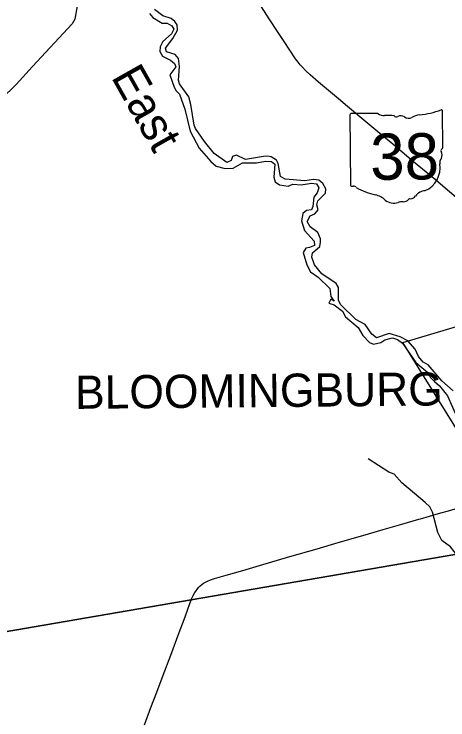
# Model space of a CAD drawing. Extents: x -51392 to 1635000, y 156707 to 696232.
# Drawn here: x 142132 to 148661, y 507736 to 518358 of the extents above; entities that cross this region are included whole.
import ezdxf

# ---------------------------------------------------------------- set-up
doc = ezdxf.new("R2010")
doc.units = 0
for name, color, linetype in [('GM_X_Corporation', 7, 'Continuous'), ('GM_X_Corporation_Text', 7, 'Continuous'), ('GM_X_Minor_River', 7, 'Continuous'), ('GM_X_Minor_River_Text', 7, 'Continuous'), ('GM_X_State_Route', 7, 'Continuous'), ('GM_X_State_Shield', 7, 'Continuous'), ('GM_X_Township', 7, 'Continuous')]:
    doc.layers.add(name, color=color, linetype=linetype)

msp = doc.modelspace()

# ---------------------------------------------------------------- linework, layer by layer
at = {"layer": 'GM_X_Corporation'}
msp.add_lwpolyline([(151122, 510634), (149846, 510420), (147983, 513415), (149817, 513960), (149380, 514705), (149899, 514933), (151298, 515355), (151165, 515855), (151597, 515995), (154267, 511567), (151620, 510720), (151716, 510504), (151268, 510327)], close=True, dxfattribs=at)
at = {"layer": 'GM_X_Minor_River'}
for points in [[(144055, 518872), (143223, 518622), (143173, 518604), (143109, 518555), (143080, 518482), (143046, 518284), (143005, 518212), (142408, 517569), (142163, 517297), (141940, 517082), (141639, 516862), (141521, 516751), (141472, 516673), (141395, 516408), (141367, 516342), (141275, 516249), (141124, 516197), (140980, 516203)], [(144172, 518369), (144218, 518307), (144362, 518222), (144434, 518220), (144504, 518183), (144538, 518129), (144503, 518061), (144371, 517945), (144331, 517865), (144326, 517795), (144364, 517723), (144488, 517663), (144546, 517614), (144566, 517564), (144475, 517446), (144542, 517256), (144572, 517204), (144620, 517151), (144703, 516927), (144782, 516596), (144915, 516339), (145092, 516138), (145172, 516070), (145308, 516035), (145430, 516039), (145572, 516121), (145780, 516122), (145915, 516146), (146005, 516139), (146056, 516097), (146040, 515905), (146063, 515833), (146127, 515790), (146257, 515768), (146329, 515796), (146455, 515789), (146608, 515813), (146682, 515803), (146717, 515744), (146693, 515668), (146641, 515604), (146626, 515464), (146606, 515412), (146534, 515402), (146478, 515355), (146459, 515246), (146501, 515100), (146646, 514939), (146654, 514877), (146578, 514845), (146522, 514834), (146485, 514768), (146537, 514583), (146592, 514477), (146706, 514400), (146884, 514229), (146899, 514107), (146951, 514039), (146897, 514067), (146871, 514009), (146949, 513983), (147074, 513886), (147120, 513804), (147311, 513643), (147379, 513521), (147483, 513414), (147543, 513390), (147653, 513414), (147711, 513456), (147827, 513485), (147905, 513463), (147979, 513407), (148176, 513117), (148359, 512963), (148393, 512896), (148459, 512828), (148535, 512764), (148654, 512615), (148807, 512274)], [(148742, 512687), (148569, 512838), (148362, 513077), (148288, 513119), (148218, 513203), (148169, 513316), (148057, 513440), (147941, 513503), (147777, 513551), (147587, 513484), (147517, 513540), (147414, 513687), (147276, 513763), (147045, 513988), (147015, 514051), (147012, 514241), (146980, 514303), (146762, 514448), (146653, 514583), (146615, 514699), (146623, 514765), (146734, 514861), (146746, 514925), (146742, 514975), (146705, 515069), (146587, 515154), (146543, 515236), (146590, 515320), (146658, 515350), (146710, 515412), (146688, 515486), (146701, 515546), (146821, 515664), (146823, 515730), (146780, 515806), (146718, 515859), (146638, 515871), (146508, 515851), (146210, 515872), (146142, 515913), (146105, 516111), (146079, 516161), (145999, 516209), (145945, 516218), (145885, 516214), (145615, 516171), (145481, 516237), (145421, 516213), (145400, 516153), (145334, 516127), (145143, 516260), (144999, 516443), (144862, 516636), (144840, 516688), (144793, 516999), (144760, 517113), (144621, 517306), (144605, 517362), (144622, 517568), (144606, 517688), (144556, 517751), (144426, 517791), (144411, 517847), (144523, 517989), (144592, 518117), (144584, 518195), (144552, 518247), (144498, 518294), (144368, 518332), (144243, 518425)], [(148809, 510199), (148701, 510341), (148569, 510436), (148510, 510554), (148427, 510863), (148389, 510943), (148321, 511007), (147969, 511305), (147853, 511434), (147771, 511466), (147462, 511663)]]:
    msp.add_lwpolyline(points, dxfattribs=at)
at = {"layer": 'GM_X_State_Route'}
for points in [[(148888, 515514), (148586, 515767), (148473, 515862), (148334, 515977), (148145, 516135), (147831, 516398), (147667, 516535), (147428, 516735), (147152, 516967), (147013, 517082), (146712, 517336), (146589, 517445), (146517, 517511), (146471, 517558), (146439, 517595), (146408, 517633), (146369, 517685), (146195, 517944), (146106, 518081), (145970, 518287), (145819, 518521)], [(148249, 510763), (148522, 510841), (148704, 510894), (148868, 510941), (149073, 511002), (149425, 511103)], [(144095, 507661), (144192, 507922), (144279, 508152), (144360, 508367), (144506, 508751), (144602, 509012), (144706, 509289), (144779, 509489), (144799, 509540), (144809, 509566), (144829, 509610), (144853, 509653), (144870, 509680), (144890, 509706), (144911, 509731), (144934, 509753), (144959, 509774), (144985, 509793), (145013, 509810), (145042, 509824), (145087, 509843), (145149, 509863), (145322, 509914), (145575, 509986), (145827, 510060), (146283, 510193), (146693, 510311), (147008, 510404), (147277, 510479), (147466, 510535), (147686, 510600), (147970, 510681), (148222, 510755), (148249, 510763)]]:
    msp.add_lwpolyline(points, dxfattribs=at)
at = {"layer": 'GM_X_State_Shield'}
for p, q in [((147609, 516864), (147201, 516860)), ((148584, 516346), (148579, 516899)), ((147187, 516841), (147197, 515785)), ((148584, 516346), (148584, 516346))]:
    msp.add_line(p, q, dxfattribs=at)
for centre, radius, start, end in [((147203, 516844), 16.1, 98.6686, 188.6686), ((147704, 516987), 156, 232.1581, 271.6504), ((148070, 518308), 1476, 276.383, 289.445), ((148564, 516901), 15.5, 352.4006, 98.2765), ((147763, 516272), 562, 81.0252, 95.5268), ((147885, 516856), 45.1, 220.3306, 297.6409), ((147952, 516734), 93.8, 55.0052, 119.6797), ((148072, 516903), 113, 234.3948, 295.3667), ((148275, 516547), 297, 97.8847, 121.3074), ((148581, 516306), 24, 108.4825, 210.8755), ((148568, 516344), 16.6, 290.1424, 8.2727), ((148429, 516234), 144, 340.5715, 24.1881), ((148642, 516115), 105, 137.345, 187.4681), ((148174, 516041), 369, 292.8474, 9.5244), ((147213, 515783), 16.3, 172.4969, 258.8452), ((147215, 515891), 124, 267.8775, 281.1424), ((147242, 515724), 44.8, 30.2869, 93.8103), ((147798, 516679), 1066, 240.9515, 257.737), ((148335, 515499), 202, 94.9417, 143.1153), ((147493, 515313), 334, 47.7227, 76.3745), ((148091, 515546), 31.8, 66.2903, 133.187), ((148077, 515691), 119, 283.4117, 323.8157), ((147850, 515725), 212, 231.2389, 286.8304), ((147976, 515361), 174, 86.2337, 111.7485), ((147989, 515647), 113, 269.3156, 316.0878)]:
    msp.add_arc(centre, radius, start, end, dxfattribs=at)
at = {"layer": 'GM_X_Township'}
for points in [[(156615, 518610), (156029, 512335), (155947, 511459), (154498, 511210), (151626, 510716), (144799, 509542), (137879, 508352), (135814, 507997), (131842, 506508), (126804, 504618)], [(137879, 508352), (144799, 509542), (151626, 510716), (154498, 511210), (155947, 511459), (155787, 509753), (155247, 503773), (155421, 503418), (155960, 502573), (156062, 502444), (156249, 502283), (156897, 501677), (157103, 501507), (157429, 501318), (157691, 501158), (158040, 500911), (158676, 500430), (159105, 500105), (159714, 499486)]]:
    msp.add_lwpolyline(points, dxfattribs=at)

# ---------------------------------------------------------------- texts
at = {"layer": 'GM_X_Corporation_Text'}
msp.add_text('BLOOMINGBURG', height=500, rotation=0.5386, dxfattribs=at).set_placement((143051, 512416))
at = {"layer": 'GM_X_Minor_River_Text'}
msp.add_text('East', height=500, rotation=299.394, dxfattribs=at).set_placement((143585, 517412))
at = {"layer": 'GM_X_State_Shield'}
msp.add_text('38', height=696.1, rotation=0.5385, dxfattribs=at).set_placement((147495, 515862))

doc.saveas('drawing.dxf')
